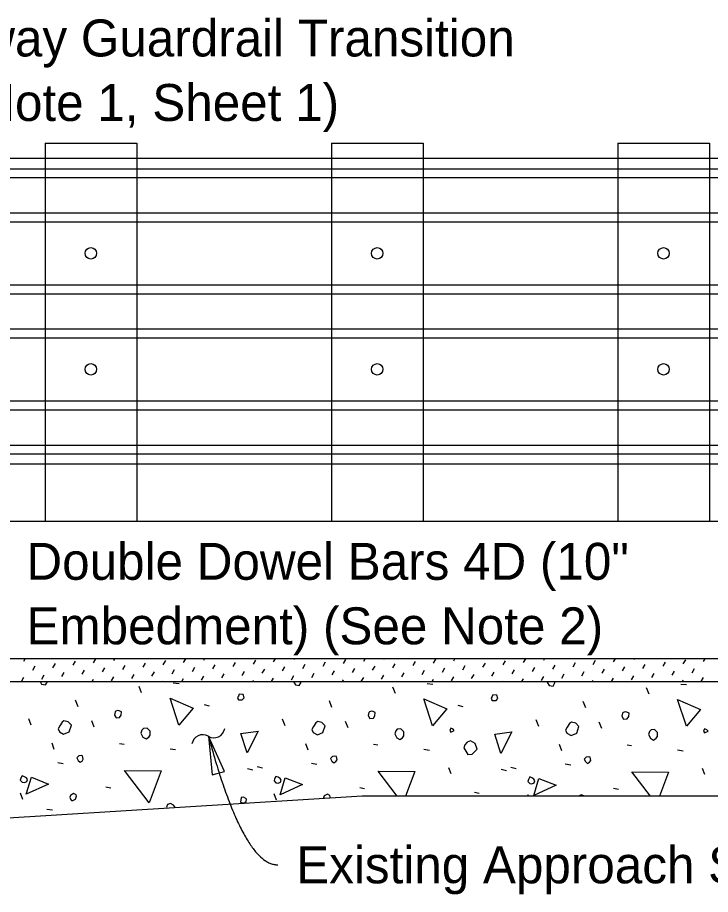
# Model space of a CAD drawing. Extents: x 21526.6 to 21598.7, y 56118.9 to 56155.9.
# Drawn here: x 21557.641 to 21561.422, y 56133.174 to 56137.959 of the extents above; entities that cross this region are included whole.
import ezdxf

# ---------------------------------------------------------------- set-up
doc = ezdxf.new("R2010")
doc.units = 0
for name, color, linetype in [('AdhocPoint_dp', 7, 'Continuous'), ('Border', 7, 'Continuous'), ('Patterning', 7, 'Continuous'), ('PlotBorder_dp', 7, 'Continuous'), ('SheetBorder_dp', 7, 'Continuous')]:
    doc.layers.add(name, color=color, linetype=linetype)

msp = doc.modelspace()

# ---------------------------------------------------------------- linework, layer by layer
at = {"layer": 'AdhocPoint_dp'}
for p, q in [((21554.3018, 56135.21), (21562.4118, 56135.21)), ((21565.8764, 56134.4601), (21554.3018, 56134.4601)), ((21554.3018, 56134.3351), (21565.8764, 56134.3351)), ((21559.5217, 56133.71), (21555.5217, 56133.46)), ((21565.8764, 56133.71), (21559.5217, 56133.71))]:
    msp.add_line(p, q, dxfattribs=at)
at = {"layer": 'Patterning'}
for p, q in [((21557.7913, 56137.2725), (21557.7913, 56135.21)), ((21557.7913, 56137.2725), (21558.2913, 56137.2725)), ((21558.2913, 56137.2725), (21558.2913, 56135.21)), ((21559.3538, 56137.2725), (21559.3538, 56135.21)), ((21559.3538, 56137.2725), (21559.8538, 56137.2725)), ((21559.8538, 56137.2725), (21559.8538, 56135.21)), ((21560.9163, 56137.2725), (21560.9163, 56135.21)), ((21560.9163, 56137.2725), (21561.4163, 56137.2725)), ((21561.4163, 56137.2725), (21561.4163, 56135.21)), ((21557.6751, 56134.447), (21557.6827, 56134.4601)), ((21557.7857, 56134.4599), (21557.7858, 56134.4601)), ((21557.9452, 56134.424), (21557.9581, 56134.4464)), ((21558.0558, 56134.437), (21558.0688, 56134.4594)), ((21558.1664, 56134.45), (21558.1723, 56134.4601)), ((21558.4365, 56134.4271), (21558.4495, 56134.4495)), ((21558.5472, 56134.44), (21558.5588, 56134.4601)), ((21558.6578, 56134.453), (21558.6619, 56134.4601)), ((21558.9279, 56134.4301), (21558.9409, 56134.4525)), ((21559.0385, 56134.4431), (21559.0484, 56134.4601)), ((21559.1492, 56134.456), (21559.1515, 56134.4601)), ((21559.4193, 56134.4331), (21559.4322, 56134.4555)), ((21559.5299, 56134.4461), (21559.538, 56134.4601)), ((21559.6405, 56134.459), (21559.6412, 56134.4601)), ((21559.8, 56134.4232), (21559.813, 56134.4456)), ((21559.9106, 56134.4361), (21559.9236, 56134.4585)), ((21560.0213, 56134.4491), (21560.0276, 56134.4601)), ((21560.2914, 56134.4262), (21560.3043, 56134.4486)), ((21560.402, 56134.4391), (21560.4141, 56134.4601)), ((21560.5126, 56134.4521), (21560.5173, 56134.4601)), ((21560.7827, 56134.4292), (21560.7957, 56134.4516)), ((21560.8934, 56134.4422), (21560.9038, 56134.4601)), ((21561.004, 56134.4551), (21561.0069, 56134.4601)), ((21561.2741, 56134.4322), (21561.2871, 56134.4546)), ((21561.3847, 56134.4452), (21561.3934, 56134.4601)), ((21557.7239, 56134.3981), (21557.7369, 56134.4205)), ((21557.8345, 56134.4111), (21557.8475, 56134.4335)), ((21557.994, 56134.3752), (21558.007, 56134.3976)), ((21558.1046, 56134.3882), (21558.1176, 56134.4106)), ((21558.2153, 56134.4011), (21558.2282, 56134.4235)), ((21558.3259, 56134.4141), (21558.3389, 56134.4365)), ((21558.4854, 56134.3782), (21558.4983, 56134.4006)), ((21558.596, 56134.3912), (21558.609, 56134.4136)), ((21558.7066, 56134.4042), (21558.7196, 56134.4266)), ((21558.8173, 56134.4171), (21558.8302, 56134.4395)), ((21558.9767, 56134.3813), (21558.9897, 56134.4036)), ((21559.0874, 56134.3942), (21559.1003, 56134.4166)), ((21559.198, 56134.4072), (21559.211, 56134.4296)), ((21559.3086, 56134.4201), (21559.3216, 56134.4425)), ((21559.4681, 56134.3843), (21559.4811, 56134.4067)), ((21559.5787, 56134.3972), (21559.5917, 56134.4196)), ((21559.6894, 56134.4102), (21559.7023, 56134.4326)), ((21559.9595, 56134.3873), (21559.9724, 56134.4097)), ((21560.0701, 56134.4003), (21560.0831, 56134.4226)), ((21560.1807, 56134.4132), (21560.1937, 56134.4356)), ((21560.3402, 56134.3774), (21560.3532, 56134.3997)), ((21560.4508, 56134.3903), (21560.4638, 56134.4127)), ((21560.5615, 56134.4033), (21560.5744, 56134.4257)), ((21560.6721, 56134.4162), (21560.6851, 56134.4386)), ((21560.8316, 56134.3804), (21560.8445, 56134.4028)), ((21560.9422, 56134.3933), (21560.9552, 56134.4157)), ((21561.0528, 56134.4063), (21561.0658, 56134.4287)), ((21561.1635, 56134.4193), (21561.1764, 56134.4417)), ((21561.3229, 56134.3834), (21561.3359, 56134.4058)), ((21557.6621, 56134.3363), (21557.6751, 56134.3587)), ((21557.7727, 56134.3493), (21557.7857, 56134.3717)), ((21557.8834, 56134.3623), (21557.8963, 56134.3846)), ((21558.1535, 56134.3393), (21558.1664, 56134.3617)), ((21558.2641, 56134.3523), (21558.2771, 56134.3747)), ((21558.3747, 56134.3653), (21558.3877, 56134.3877)), ((21558.5375, 56134.3351), (21558.5472, 56134.3518)), ((21558.6448, 56134.3424), (21558.6578, 56134.3648)), ((21558.7555, 56134.3553), (21558.7684, 56134.3777)), ((21558.8661, 56134.3683), (21558.8791, 56134.3907)), ((21559.0271, 56134.3351), (21559.0385, 56134.3548)), ((21559.1362, 56134.3454), (21559.1492, 56134.3678)), ((21559.2468, 56134.3583), (21559.2598, 56134.3807)), ((21559.3575, 56134.3713), (21559.3704, 56134.3937)), ((21559.5169, 56134.3354), (21559.5299, 56134.3578)), ((21559.6276, 56134.3484), (21559.6405, 56134.3708)), ((21559.7382, 56134.3614), (21559.7512, 56134.3838)), ((21559.8488, 56134.3743), (21559.8618, 56134.3967)), ((21560.0083, 56134.3385), (21560.0213, 56134.3609)), ((21560.1189, 56134.3514), (21560.1319, 56134.3738)), ((21560.2296, 56134.3644), (21560.2425, 56134.3868)), ((21560.3928, 56134.3351), (21560.402, 56134.3509)), ((21560.4997, 56134.3415), (21560.5126, 56134.3639)), ((21560.6103, 56134.3544), (21560.6233, 56134.3768)), ((21560.7209, 56134.3674), (21560.7339, 56134.3898)), ((21560.8824, 56134.3351), (21560.8934, 56134.3539)), ((21560.991, 56134.3445), (21561.004, 56134.3669)), ((21561.1017, 56134.3575), (21561.1146, 56134.3799)), ((21561.2123, 56134.3704), (21561.2253, 56134.3928)), ((21561.3721, 56134.3351), (21561.3847, 56134.3569)), ((21557.9447, 56134.3351), (21557.9452, 56134.3358)), ((21558.0479, 56134.3351), (21558.0558, 56134.3488)), ((21558.3181, 56134.2732), (21558.304, 56134.3085)), ((21558.4343, 56134.3351), (21558.4365, 56134.3388)), ((21558.4907, 56134.3291), (21558.5225, 56134.3256)), ((21558.924, 56134.3351), (21558.9279, 56134.3418)), ((21559.4136, 56134.3351), (21559.4193, 56134.3449)), ((21559.7028, 56134.2696), (21559.6886, 56134.305)), ((21559.8754, 56134.3256), (21559.9072, 56134.322)), ((21559.9032, 56134.3351), (21559.9106, 56134.3479)), ((21560.2897, 56134.3351), (21560.2914, 56134.3379)), ((21560.7793, 56134.3351), (21560.7827, 56134.341)), ((21561.2601, 56134.322), (21561.2919, 56134.3185)), ((21561.2689, 56134.3351), (21561.2741, 56134.344)), ((21561.0875, 56134.2661), (21561.0733, 56134.3014)), ((21557.9723, 56134.1983), (21557.9581, 56134.2336)), ((21558.6587, 56134.2107), (21558.6869, 56134.2036)), ((21559.3569, 56134.1947), (21559.3428, 56134.2301)), ((21560.0433, 56134.2071), (21560.0716, 56134.2001)), ((21560.7416, 56134.1912), (21560.7275, 56134.2266)), ((21557.7159, 56134.0975), (21557.7018, 56134.1329)), ((21558.06, 56134.0858), (21558.0459, 56134.1211)), ((21559.1006, 56134.094), (21559.0865, 56134.1293)), ((21559.4447, 56134.0822), (21559.4306, 56134.1176)), ((21560.4853, 56134.0904), (21560.4711, 56134.1258)), ((21560.8294, 56134.0787), (21560.8152, 56134.1141)), ((21557.8414, 56133.9649), (21557.8291, 56133.9985)), ((21558.1979, 56133.9974), (21558.2227, 56133.9938)), ((21558.4737, 56133.9691), (21558.5037, 56133.9638)), ((21559.2261, 56133.9614), (21559.2137, 56133.995)), ((21559.5826, 56133.9938), (21559.6073, 56133.9903)), ((21560.6108, 56133.9579), (21560.5984, 56133.9915)), ((21560.9673, 56133.9903), (21560.992, 56133.9868)), ((21559.8584, 56133.9656), (21559.8884, 56133.9603)), ((21561.243, 56133.962), (21561.2731, 56133.9567)), ((21557.8603, 56133.8931), (21557.8903, 56133.8878)), ((21558.9486, 56133.8712), (21558.9769, 56133.8642)), ((21559.2449, 56133.8895), (21559.275, 56133.8842)), ((21560.6296, 56133.886), (21560.6597, 56133.8807)), ((21558.8962, 56133.8613), (21558.9245, 56133.8542)), ((21560.0068, 56133.8312), (21559.9945, 56133.8648)), ((21560.2808, 56133.8577), (21560.3091, 56133.8507)), ((21560.3333, 56133.8677), (21560.3615, 56133.8606)), ((21561.3915, 56133.8277), (21561.3791, 56133.8613)), ((21558.1237, 56133.7605), (21558.1502, 56133.7552)), ((21559.5083, 56133.757), (21559.5349, 56133.7517)), ((21560.1341, 56133.7322), (21560.1606, 56133.7269)), ((21560.893, 56133.7534), (21560.9195, 56133.7481)), ((21557.67, 56133.6922), (21557.6576, 56133.7258)), ((21559.0546, 56133.6887), (21559.0423, 56133.7222)), ((21560.4301, 56133.71), (21560.4269, 56133.7187)), ((21557.8002, 56133.6385), (21557.832, 56133.635))]:
    msp.add_line(p, q, dxfattribs=at)
for points in [[(21557.7643, 56134.3351), (21557.7725, 56134.3203), (21557.7937, 56134.3167), (21557.8026, 56134.3326), (21557.8032, 56134.3351)], [(21559.1471, 56134.3351), (21559.1483, 56134.3326)], [(21559.1483, 56134.3326), (21559.1572, 56134.3167), (21559.1784, 56134.3132), (21559.1872, 56134.3291), (21559.1887, 56134.3351)], [(21560.53, 56134.3351), (21560.533, 56134.3291)], [(21560.533, 56134.3291), (21560.5419, 56134.3132), (21560.5631, 56134.3097), (21560.5719, 56134.3256), (21560.5743, 56134.3351)], [(21558.846, 56134.2354), (21558.8673, 56134.2354), (21558.8779, 56134.246), (21558.8726, 56134.2655), (21558.8496, 56134.2672), (21558.846, 56134.2566), (21558.8407, 56134.2478), (21558.846, 56134.2354), (21558.8425, 56134.2389)], [(21560.2307, 56134.2319), (21560.2519, 56134.2319), (21560.2625, 56134.2425), (21560.2572, 56134.2619), (21560.2343, 56134.2637), (21560.2307, 56134.2531), (21560.2254, 56134.2442), (21560.2307, 56134.2319), (21560.2272, 56134.2354)], [(21558.5214, 56134.0981), (21558.4737, 56134.2449), (21558.5992, 56134.1901), (21558.5214, 56134.0981)], [(21559.9061, 56134.0946), (21559.8584, 56134.2413), (21559.9839, 56134.1865), (21559.9061, 56134.0946)], [(21561.2908, 56134.0911), (21561.243, 56134.2378), (21561.3685, 56134.183), (21561.2908, 56134.0911)], [(21558.1696, 56134.1529), (21558.1785, 56134.137), (21558.1979, 56134.1388), (21558.2067, 56134.1512), (21558.2085, 56134.1706), (21558.1961, 56134.1759), (21558.1873, 56134.1777), (21558.1767, 56134.1742), (21558.1732, 56134.1706), (21558.1696, 56134.1529)], [(21559.5543, 56134.1494), (21559.5631, 56134.1335), (21559.5826, 56134.1353), (21559.5914, 56134.1476), (21559.5932, 56134.1671), (21559.5808, 56134.1724), (21559.572, 56134.1742), (21559.5614, 56134.1706), (21559.5578, 56134.1671), (21559.5543, 56134.1494)], [(21560.939, 56134.1459), (21560.9478, 56134.13), (21560.9673, 56134.1317), (21560.9761, 56134.1441), (21560.9779, 56134.1636), (21560.9655, 56134.1689), (21560.9567, 56134.1706), (21560.946, 56134.1671), (21560.9425, 56134.1636), (21560.939, 56134.1459)], [(21557.8697, 56134.0604), (21557.8927, 56134.048), (21557.9228, 56134.0604), (21557.9351, 56134.0975), (21557.9175, 56134.1152), (21557.8945, 56134.1205), (21557.8839, 56134.1134), (21557.8715, 56134.094), (21557.8627, 56134.0781), (21557.8697, 56134.0604)], [(21559.2544, 56134.0569), (21559.2774, 56134.0445), (21559.3074, 56134.0569), (21559.3198, 56134.094), (21559.3021, 56134.1117), (21559.2792, 56134.117), (21559.2685, 56134.1099), (21559.2562, 56134.0904), (21559.2473, 56134.0745), (21559.2544, 56134.0569)], [(21560.6391, 56134.0533), (21560.6621, 56134.041), (21560.6921, 56134.0533), (21560.7045, 56134.0904), (21560.6868, 56134.1081), (21560.6638, 56134.1134), (21560.6532, 56134.1064), (21560.6408, 56134.0869), (21560.632, 56134.071), (21560.6391, 56134.0533)], [(21558.3146, 56134.054), (21558.3252, 56134.0327), (21558.3429, 56134.0221), (21558.357, 56134.0327), (21558.3641, 56134.0433), (21558.3641, 56134.0646), (21558.3482, 56134.0805), (21558.3287, 56134.0787), (21558.3199, 56134.0699), (21558.3146, 56134.054)], [(21558.8938, 56133.9473), (21558.8602, 56134.0516), (21558.9539, 56134.0639), (21558.8938, 56133.9473)], [(21559.6993, 56134.0504), (21559.7099, 56134.0292), (21559.7275, 56134.0186), (21559.7417, 56134.0292), (21559.7488, 56134.0398), (21559.7488, 56134.061), (21559.7328, 56134.0769), (21559.7134, 56134.0752), (21559.7046, 56134.0663), (21559.6993, 56134.0504)], [(21560.0051, 56134.0593), (21560.0245, 56134.0681), (21560.0175, 56134.0752), (21560.0051, 56134.0805), (21559.9998, 56134.0681), (21560.0051, 56134.0593)], [(21561.0839, 56134.0469), (21561.0945, 56134.0257), (21561.1122, 56134.0151), (21561.1264, 56134.0257), (21561.1334, 56134.0363), (21561.1334, 56134.0575), (21561.1175, 56134.0734), (21561.0981, 56134.0716), (21561.0892, 56134.0628), (21561.0839, 56134.0469)], [(21561.3898, 56134.0557), (21561.4092, 56134.0646), (21561.4021, 56134.0716), (21561.3898, 56134.0769), (21561.3845, 56134.0646), (21561.3898, 56134.0557)], [(21560.2785, 56133.9437), (21560.2449, 56134.048), (21560.3386, 56134.0604), (21560.2785, 56133.9437)], [(21560.0758, 56133.9744), (21560.0988, 56133.9373), (21560.1218, 56133.939), (21560.1306, 56133.9479), (21560.15, 56133.9673), (21560.1377, 56133.9974), (21560.1129, 56134.0115), (21560.0952, 56134.0045), (21560.0811, 56133.9903), (21560.0758, 56133.9744)], [(21557.9716, 56133.9055), (21557.9822, 56133.8949), (21557.9928, 56133.9019), (21557.9999, 56133.9125), (21557.9964, 56133.9302), (21557.9875, 56133.932), (21557.9752, 56133.9302), (21557.9646, 56133.9196), (21557.9716, 56133.9055)], [(21559.3563, 56133.9019), (21559.3669, 56133.8913), (21559.3775, 56133.8984), (21559.3846, 56133.909), (21559.3811, 56133.9267), (21559.3722, 56133.9284), (21559.3598, 56133.9267), (21559.3492, 56133.9161), (21559.3563, 56133.9019)], [(21560.741, 56133.8984), (21560.7516, 56133.8878), (21560.7622, 56133.8949), (21560.7693, 56133.9055), (21560.7657, 56133.9231), (21560.7569, 56133.9249), (21560.7445, 56133.9231), (21560.7339, 56133.9125), (21560.741, 56133.8984)], [(21558.3588, 56133.6739), (21558.2244, 56133.8507), (21558.4242, 56133.8489), (21558.3588, 56133.6739)], [(21559.7133, 56133.71), (21559.6091, 56133.8471), (21559.8089, 56133.8454), (21559.7583, 56133.71)], [(21561.0953, 56133.71), (21560.9938, 56133.8436), (21561.1935, 56133.8418), (21561.1443, 56133.71)], [(21557.6664, 56133.7864), (21557.6788, 56133.7846), (21557.6912, 56133.7899), (21557.6947, 56133.8005), (21557.6894, 56133.8094), (21557.6788, 56133.8164), (21557.6664, 56133.8217), (21557.6594, 56133.8076), (21557.6558, 56133.797), (21557.6664, 56133.7864)], [(21557.6888, 56133.7216), (21557.7171, 56133.8135), (21557.8108, 56133.7764), (21557.6888, 56133.7216)], [(21559.0511, 56133.7829), (21559.0635, 56133.7811), (21559.0759, 56133.7864), (21559.0794, 56133.797), (21559.0741, 56133.8058), (21559.0635, 56133.8129), (21559.0511, 56133.8182), (21559.044, 56133.8041), (21559.0405, 56133.7935), (21559.0511, 56133.7829)], [(21559.0735, 56133.7181), (21559.1017, 56133.81), (21559.1954, 56133.7729), (21559.0735, 56133.7181)], [(21560.4358, 56133.7793), (21560.4482, 56133.7776), (21560.4605, 56133.7829), (21560.4641, 56133.7935), (21560.4588, 56133.8023), (21560.4482, 56133.8094), (21560.4358, 56133.8147), (21560.4287, 56133.8005), (21560.4252, 56133.7899), (21560.4358, 56133.7793)], [(21560.4581, 56133.7145), (21560.4864, 56133.8065), (21560.5801, 56133.7693), (21560.4581, 56133.7145)], [(21557.9363, 56133.6863), (21557.9433, 56133.6863), (21557.9575, 56133.6933), (21557.9628, 56133.7092), (21557.961, 56133.7181), (21557.9469, 56133.7251), (21557.9292, 56133.7145), (21557.9257, 56133.7039), (21557.9292, 56133.6933), (21557.9363, 56133.6863)], [(21558.8573, 56133.6774), (21558.8767, 56133.6721), (21558.8891, 56133.681), (21558.8909, 56133.6933), (21558.8873, 56133.6969), (21558.8732, 56133.7039), (21558.8608, 56133.7022), (21558.859, 56133.6898), (21558.8573, 56133.6774)], [(21559.3452, 56133.699), (21559.3475, 56133.7057), (21559.3457, 56133.7145), (21559.3316, 56133.7216), (21559.3139, 56133.711), (21559.3103, 56133.7004), (21559.3115, 56133.6969)], [(21560.7306, 56133.71), (21560.7304, 56133.711), (21560.7162, 56133.7181), (21560.7028, 56133.71)], [(21558.4985, 56133.6461), (21558.5002, 56133.6527), (21558.4914, 56133.6615), (21558.4754, 56133.6703), (21558.4595, 56133.665), (21558.4542, 56133.6491), (21558.4571, 56133.6435)]]:
    msp.add_lwpolyline(points, dxfattribs=at)
at = {"layer": 'PlotBorder_dp'}
msp.add_lwpolyline([(21558.6823, 56134.0371), (21558.7024, 56133.8269), (21558.7706, 56133.8452)], close=True, dxfattribs=at)
for centre, start, end in [((21558.7125, 56134.0879), 239.2651, 350.9923), ((21558.6515, 56133.9854), 59.2651, 170.9923)]:
    msp.add_arc(centre, 0.0596, start, end, dxfattribs=at)
msp.add_open_spline([(21558.6827, 56134.0369), (21558.8719, 56133.3352), (21559.061, 56133.3352)], degree=2, dxfattribs=at)
at = {"layer": 'SheetBorder_dp'}
for p, q in [((21564.1633, 56137.1891), (21552.8484, 56137.1891)), ((21552.8484, 56137.1336), (21564.1633, 56137.1336)), ((21552.8484, 56137.0853), (21564.1633, 56137.0853)), ((21552.8484, 56136.8925), (21564.1633, 56136.8925)), ((21552.8484, 56136.8443), (21564.1633, 56136.8443)), ((21552.8484, 56136.5003), (21564.1633, 56136.5003)), ((21552.8484, 56136.4521), (21564.1633, 56136.4521)), ((21552.8484, 56136.2593), (21564.1633, 56136.2593)), ((21552.8484, 56136.2112), (21564.1633, 56136.2112)), ((21552.8484, 56135.8672), (21564.1633, 56135.8672)), ((21552.8484, 56135.819), (21564.1633, 56135.819)), ((21552.8484, 56135.6262), (21564.1633, 56135.6262)), ((21552.8484, 56135.5779), (21564.1633, 56135.5779)), ((21564.1633, 56135.5224), (21552.8484, 56135.5224))]:
    msp.add_line(p, q, dxfattribs=at)
for centre in [(21558.0413, 56136.6724), (21559.6038, 56136.6724), (21561.1663, 56136.6724), (21558.0413, 56136.0393), (21559.6038, 56136.0393), (21561.1663, 56136.0393)]:
    msp.add_circle(centre, 0.0312, dxfattribs=at)

# ---------------------------------------------------------------- texts
at = {"layer": 'Border'}
msp.add_text('Existing Approach Slab', height=0.2016, dxfattribs=at).set_placement((21559.1619, 56133.2344))
at = {"layer": 'PlotBorder_dp'}
for s, p in [('Roadway Guardrail Transition', (21556.788, 56137.7466)), ('(See Note 1, Sheet 1)', (21556.788, 56137.3946)), ('Double Dowel Bars 4D (10"', (21557.6898, 56134.8907)), ('Embedment) (See Note 2)', (21557.6898, 56134.5387))]:
    msp.add_text(s, height=0.2016, dxfattribs=at).set_placement(p)

doc.saveas('drawing.dxf')
